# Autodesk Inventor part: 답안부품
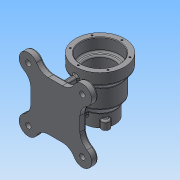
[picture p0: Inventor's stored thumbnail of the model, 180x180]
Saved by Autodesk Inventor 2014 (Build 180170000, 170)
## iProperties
Created: 2017-03
Part Number: 답안부품
Material: 일반
Document SubType Name: Modeling
Designer: NET
Density: 1 g/cm^3
Appearance: 기본값
Author: NET
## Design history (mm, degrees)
sketch "스케치2"
  geometry: L1 (0, 50)-(0, -35); L2 (27.5, -35)-(27.5, -27); L3 (27.5, -27)-(36, -15); L4 (36, -15)-(36, 19); L5 (36, 19)-(45, 30); L6 (45, 30)-(45, 50); L7 (45, 50)-(0, 50); L8 (27.5, -35)-(0, -35); 2 further points
  constraints: 16 end point, 3 parallel, 2 coincident, 2 perpendicular, 1 point on line, 1 vertical
  dimensions: "d6" = 90 diameter of L6.end L1; "d7" = 20 distance of L5.end L6.end; "d8" = 31 vertical distance of L4.end L6.end; "d9" = 65 vertical distance of L6.end L3.end; "d10" = 55 diameter of L2.end L1; "d14" = 72 diameter of L4 L1; "d20" = 85 distance of L1.end L1.start
revolve "회전1" sketch "스케치2" stored, may be unused: angle "d18" = 90 deg
sketch "스케치4"
  geometry: C1 r 27.5 at (0, 0) reference; C2 r 27.5 at (0, 0); C3 r 7 at (0, 27.5); C4 r 7 at (-23.816, -13.75); C5 r 7 at (23.816, -13.75)
  constraints: 4 centre point, 1 coincident, 1 vertical alignment, 7 other
  dimensions: "d21" = 55 diameter of C2; "d22" = 14 diameter of C3; "d23" = 27.5 distance of C1.centre C3.centre; "d26" = 360 deg dimension on C1.centre C3.centre (derived)
extrude "돌출1" join sketch "스케치4" distance "d28" = 15; taper "d29" = 0 deg
fillet "모깎기1" dims "d30" = 3
fillet "모깎기2" dims "d31" = 1
sketch "스케치5"
  geometry: L1 (-45, 50)-(45, 50) reference; L2 (45, 50)-(45, 30) reference; L3 (45, 30)-(36, 19) reference; L4 (36, 19)-(36, -15) reference; L5 (36, -15)-(27.5, -27) reference; L6 (27.5, -27)-(27.5, -34) reference; L7 (28.5, -35)-(31.5, -35) reference; L8 (34.5, -38)-(34.5, -50) reference; L9 (34.5, -50)-(-27.5, -50) reference; L10 (-27.5, -50)-(-27.5, -27) reference; L11 (-27.5, -27)-(-36, -15) reference; L12 (-36, -15)-(-36, 19) reference; L13 (-36, 19)-(-45, 30) reference; L14 (-45, 30)-(-45, 50) reference; L15 (0, 50)-(0, -50); L16 (0, -50)-(17.5, -50); L17 (17.5, -50)-(17.5, -23); L18 (20.5, -20)-(23, -20); L19 (26, -17)-(26, 24); L20 (29, 27)-(32, 27); L21 (35, 30)-(35, 50); L22 (0, 50)-(35, 50); A1 r 1 centre (28.5, -34) between (27.5, -34) and (28.5, -35) reference; A2 r 3 centre (31.5, -38) between (34.5, -38) and (31.5, -35) reference; A3 r 3 centre (32, 30) between (32, 27) and (35, 30); A4 r 3 centre (29, 24) between (29, 27) and (26, 24); A5 r 3 centre (23, -17) between (23, -20) and (26, -17); A6 r 3 centre (20.5, -23) between (20.5, -20) and (17.5, -23); 2 further points
  constraints: 16 end point, 8 point on circle, 8 tangent, 5 point on line, 4 centre point, 4 perpendicular, 2 equal radius, 2 parallel, 1 collinear, 1 midpoint
  dimensions: "d32" = 30 distance of L16.end point (17.5, -20); "d33" = 35 diameter of L17 L15; "d35" = 52 diameter of L19 L15; "d36" = 70 diameter of L21 L15; "d37" = 3 radius of A3; "d38" = 3 radius of A5; "d39" = 47 vertical distance of L20.start L18.end
revolve "회전2" sketch "스케치5" stored, may be unused: angle "d40" = 90 deg
chamfer "모따기1" distance "d41" = 1; stored, may be unused: second distance "d42" = 2, angle "d43" = 45 deg
fillet "모깎기3" dims "d44" = 3
chamfer "모따기2" distance "d45" = 1; stored, may be unused: second distance "d46" = 2, angle "d47" = 45 deg
sketch "스케치6"
  geometry: A1 r 7 centre (0, 27.5) between (6.999, 27.373) and (-6.999, 27.373) reference; 1 further point
  constraints: 1 coincident
hole "구멍1" sketch "스케치6" at (0, 27.5) diameter "d48" = 3.242; stored, may be unused: countersink angle "d52" = 90 deg, drill point angle "d54" = 118 deg; dims "d49" = 9, "d50" = 4, "d51" = 2, "d53" = 11
sketch "스케치11"
  geometry: L1 (-17.5, -49)-(-18.5, -50) reference; L2 (-18.5, -50)-(-27.5, -50) reference; L3 (-27.5, -50)-(-27.5, -27.955) reference; L4 (-28.052, -26.221)-(-35.448, -15.779) reference; L5 (-36, -14.045)-(-36, 17.929) reference; L6 (-36.678, 19.829)-(-44.322, 29.171) reference; L7 (-45, 31.071)-(-45, 50) reference; L8 (-45, 50)-(-36, 50) reference; L9 (-36, 50)-(-35, 49) reference; L10 (-35, 49)-(-35, 30) reference; L11 (-32, 27)-(-29, 27) reference; L12 (-26, 24)-(-26, -17) reference; L13 (-23, -20)-(-20.5, -20) reference; L14 (-17.5, -23)-(-17.5, -49) reference; L15 (34.5, -38)-(34.5, -50) reference; L16 (34.5, -50)-(29.121, -50) reference; L17 (29.121, -50)-(29.121, -39) reference; L18 (29.121, -39)-(27.5, -38.026) reference; L19 (27.5, -38.026)-(25.879, -39) reference; L20 (25.879, -39)-(25.879, -50) reference; L21 (25.879, -50)-(18.5, -50) reference; L22 (18.5, -50)-(17.5, -49) reference; L23 (17.5, -49)-(17.5, -23) reference; L24 (20.5, -20)-(23, -20) reference; L25 (26, -17)-(26, 24) reference; L26 (29, 27)-(32, 27) reference; L27 (35, 30)-(35, 49) reference; L28 (35, 49)-(36, 50) reference; L29 (36, 50)-(45, 50) reference; L30 (45, 50)-(45, 31.071) reference; L31 (44.322, 29.171)-(36.678, 19.829) reference; L32 (36, 17.929)-(36, -14.045) reference; L33 (35.448, -15.779)-(28.052, -26.221) reference; L34 (27.5, -27.955)-(27.5, -34) reference; L35 (28.5, -35)-(31.5, -35) reference; L36 (-36, 1.942)-(-70, 1.942); L37 (-70, 1.942)-(-70, -35.058); L38 (-70, -35.058)-(-27.5, -35.058); A1 r 3 centre (-30.5, -27.955) between (-27.5, -27.955) and (-28.052, -26.221) reference; A2 r 3 centre (-33, -14.045) between (-36, -14.045) and (-35.448, -15.779) reference; A3 r 3 centre (-39, 17.929) between (-36, 17.929) and (-36.678, 19.829) reference; A4 r 3 centre (-42, 31.071) between (-45, 31.071) and (-44.322, 29.171) reference; A5 r 3 centre (-32, 30) between (-35, 30) and (-32, 27) reference; A6 r 3 centre (-29, 24) between (-26, 24) and (-29, 27) reference; A7 r 3 centre (-23, -17) between (-26, -17) and (-23, -20) reference; A8 r 3 centre (-20.5, -23) between (-17.5, -23) and (-20.5, -20) reference; A9 r 3 centre (31.5, -38) between (34.5, -38) and (31.5, -35) reference; A10 r 3 centre (20.5, -23) between (20.5, -20) and (17.5, -23) reference; A11 r 3 centre (23, -17) between (23, -20) and (26, -17) reference; A12 r 3 centre (29, 24) between (29, 27) and (26, 24) reference; A13 r 3 centre (32, 30) between (32, 27) and (35, 30) reference; A14 r 3 centre (42, 31.071) between (44.322, 29.171) and (45, 31.071) reference; A15 r 3 centre (39, 17.929) between (36.678, 19.829) and (36, 17.929) reference; A16 r 3 centre (33, -14.045) between (35.448, -15.779) and (36, -14.045) reference; A17 r 3 centre (30.5, -27.955) between (28.052, -26.221) and (27.5, -27.955) reference; A18 r 1 centre (28.5, -34) between (27.5, -34) and (28.5, -35) reference; 1 further point
  constraints: 6 end point, 2 perpendicular, 1 midpoint, 1 parallel, 1 point on line
  dimensions: "d117" = 37 distance of L36.end L37.end; "d118" = 70 horizontal distance of L36.end point (0, 0)
feature "리브4" sketch "스케치11" dims "d101" = 1, "d102" = 8, "d103" = 0, "d104" = 0, "d105" = 1, "d106" = 1
node "작업 평면3"
sketch "스케치14"
  geometry: L1 (-45, 31.071)-(-45, 50) reference; L2 (-45, 50)-(-36, 50) reference; L3 (-36, 50)-(-35, 49) reference; L4 (-35, 49)-(-35, 30) reference; L5 (-32, 27)-(-29, 27) reference; L6 (-26, 24)-(-26, -17) reference; L7 (-23, -20)-(-20.5, -20) reference; L8 (-17.5, -23)-(-17.5, -49) reference; L9 (-17.5, -49)-(-18.5, -50) reference; L10 (-18.5, -50)-(-27.5, -50) reference; L11 (-27.5, -50)-(-27.5, -35.058) reference; L12 (-27.5, -35.058)-(-70, -35.058) reference; L13 (-70, -35.058)-(-70, 1.942) reference; L14 (-70, 1.942)-(-36, 1.942) reference; L15 (-36, 1.942)-(-36, 17.929) reference; L16 (-36.678, 19.829)-(-44.322, 29.171) reference; L17 (44.322, 29.171)-(36.678, 19.829) reference; L18 (36, 17.929)-(36, -14.045) reference; L19 (35.448, -15.779)-(28.052, -26.221) reference; L20 (27.5, -27.955)-(27.5, -34) reference; L21 (28.5, -35)-(31.5, -35) reference; L22 (34.5, -38)-(34.5, -50) reference; L23 (34.5, -50)-(29.121, -50) reference; L24 (29.121, -50)-(29.121, -39) reference; L25 (29.121, -39)-(27.5, -38.026) reference; L26 (27.5, -38.026)-(25.879, -39) reference; L27 (25.879, -39)-(25.879, -50) reference; L28 (25.879, -50)-(18.5, -50) reference; L29 (18.5, -50)-(17.5, -49) reference; L30 (17.5, -49)-(17.5, -23) reference; L31 (20.5, -20)-(23, -20) reference; L32 (26, -17)-(26, 24) reference; L33 (29, 27)-(32, 27) reference; L34 (35, 30)-(35, 49) reference; L35 (35, 49)-(36, 50) reference; L36 (36, 50)-(45, 50) reference; L37 (45, 50)-(45, 31.071) reference; L38 (-26, 0)-(-70, 0); L39 (-70, 0)-(-70, 37); L40 (-70, 37)-(-45, 37); A1 r 3 centre (-42, 31.071) between (-45, 31.071) and (-44.322, 29.171) reference; A2 r 3 centre (-32, 30) between (-35, 30) and (-32, 27) reference; A3 r 3 centre (-29, 24) between (-26, 24) and (-29, 27) reference; A4 r 3 centre (-23, -17) between (-26, -17) and (-23, -20) reference; A5 r 3 centre (-20.5, -23) between (-17.5, -23) and (-20.5, -20) reference; A6 r 3 centre (-39, 17.929) between (-36, 17.929) and (-36.678, 19.829) reference; A7 r 3 centre (42, 31.071) between (44.322, 29.171) and (45, 31.071) reference; A8 r 3 centre (39, 17.929) between (36.678, 19.829) and (36, 17.929) reference; A9 r 3 centre (33, -14.045) between (35.448, -15.779) and (36, -14.045) reference; A10 r 3 centre (30.5, -27.955) between (28.052, -26.221) and (27.5, -27.955) reference; A11 r 1 centre (28.5, -34) between (27.5, -34) and (28.5, -35) reference; A12 r 3 centre (31.5, -38) between (34.5, -38) and (31.5, -35) reference; A13 r 3 centre (20.5, -23) between (20.5, -20) and (17.5, -23) reference; A14 r 3 centre (23, -17) between (23, -20) and (26, -17) reference; A15 r 3 centre (29, 24) between (29, 27) and (26, 24) reference; A16 r 3 centre (32, 30) between (32, 27) and (35, 30) reference; 1 further point
  constraints: 6 end point, 4 point on line, 1 perpendicular
  dimensions: "d119" = 70 distance of point (0, 0) L38.end; "d120" = 37 distance of L38.end L39.end
feature "리브6" sketch "스케치14" dims "d121" = 1, "d122" = 8, "d123" = 0, "d124" = 0, "d125" = 1, "d126" = 1
node "작업 평면4"
sketch "스케치15"
  geometry: L1 (4, -70)-(-4, -70) reference; L2 (-4, -70)-(-4, -35.777) reference; L3 (4, -35.777)-(4, -70) reference; L4 (0, -70)-(25, -70); L5 (25, -70)-(18.14, -31.096); C1 r 26 at (0, 0) reference; A1 r 36 centre (0, 0) between (4, -35.777) and (-4, -35.777) reference; 1 further point
  constraints: 4 end point, 1 midpoint, 1 perpendicular, 1 point on circle
  dimensions: "d127" = 25 distance of L4.end L4.start; "d129" = 100 deg angle of L5 L4
feature "리브7" sketch "스케치15" dims "d131" = 1, "d132" = 8, "d133" = 0, "d134" = 0, "d135" = 1, "d136" = 1
sketch "스케치16"
  geometry: L1 (18.14, -31.096)-(25, -70) reference; L2 (25, -70)-(-4, -70) reference; L3 (-4, -70)-(-4, -35.777) reference; L4 (0, -70)-(-25, -70); L5 (-25, -70)-(-18.14, -31.096); C1 r 26 at (0, 0) reference; A1 r 36 centre (0, 0) between (18.14, -31.096) and (-4, -35.777) reference; 1 further point
  constraints: 4 end point, 1 point on circle, 1 point on line
  dimensions: "d137" = 25 distance of L4.start L4.end; "d138" = 100 deg angle of L4 L5
feature "리브8" sketch "스케치16" dims "d139" = 1, "d140" = 8, "d141" = 0, "d142" = 0, "d143" = 1, "d144" = 1
sketch "스케치17" dims "d147" = 140
  geometry: L1 (8, 0)-(0, 0) reference; L2 (29, 31.058)-(29, 39.058) reference; L3 (49, 80.058)-(-41, 80.058); L4 (-41, 80.058)-(-41, -9.942); L5 (-41, -9.942)-(49, -9.942); L6 (49, -9.942)-(49, 80.058); L7 (4, 35.058)-(53.497, -14.439); L8 (4, 35.058)-(4, -47.502); C1 r 17 at (53.497, -14.439); C2 r 17 at (53.497, 84.555); C3 r 17 at (-45.497, 84.555); C4 r 17 at (-45.497, -14.439); 5 further points
  constraints: 12 end point, 4 centre point, 4 midpoint, 3 parallel, 2 coincident, 1 horizontal, 1 horizontal alignment, 1 perpendicular, 1 vertical alignment, 12 other
  dimensions: "d145" = 90 distance of L5.end L3.start; "d146" = 90 distance of L4.end L5.end; "d148" = 45 deg angle of L8 L7; "d149" = 34 diameter of C1; "d152" = 360 deg dimension on L7.start C1.centre (derived)
extrude "돌출3" join sketch "스케치17" distance "d154" = 12; taper "d155" = 0 deg
fillet "모깎기10" dims "d156" = 3
fillet "모깎기11" dims "d157" = 3
fillet "모깎기12" dims "d158" = 25
fillet "모깎기13" dims "d159" = 3
sketch "스케치18"
  geometry: C1 r 5 at (-45.497, 14.439); C2 r 5 at (-45.497, -84.555); C3 r 5 at (53.497, -84.555); C4 r 5 at (53.497, 14.439); A1 r 14 centre (-45.497, 14.439) between (-33.279, 21.274) and (-52.332, 2.221) reference; A2 r 14 centre (-45.497, -84.555) between (-52.332, -72.337) and (-33.279, -91.39) reference; A3 r 14 centre (53.497, -84.555) between (41.279, -91.39) and (60.332, -72.337) reference; A4 r 14 centre (53.497, 14.439) between (60.332, 2.221) and (41.279, 21.274) reference; 1 further point
  constraints: 4 centre point, 4 coincident
  dimensions: "d160" = 10 diameter of C1; "d161" = 10 diameter of C2; "d162" = 10 diameter of C3; "d163" = 10 diameter of C4
extrude "돌출4" cut sketch "스케치18" stored distance "d164" = 10 (= d160); taper "d165" = 0 deg
sketch "스케치19" dims "d166" = 80
  geometry: C1 r 45 at (0, 0) reference; 2 further points
  constraints: 2 coincident, 2 vertical alignment, 2 other
hole "구멍2" sketch "스케치19" at (0, 40) diameter "d167" = 3.242; stored, may be unused: countersink angle "d171" = 90 deg, drill point angle "d173" = 118 deg; dims "d168" = 9, "d169" = 4, "d170" = 2, "d172" = 11
node "작업 평면5"
sketch "스케치20"
  geometry: C1 r 5 at (0, 0); 1 further point
  constraints: 1 centre point, 1 coincident
  dimensions: "d178" = 10 diameter of C1
extrude "돌출5" join sketch "스케치20" stored distance "d179" = 10 (= d160); taper "d180" = 0 deg
sketch "스케치21"
  geometry: C1 r 5 at (0, 0) reference; 1 further point
  constraints: 1 coincident
hole "구멍3" sketch "스케치21" at (0, 0) diameter "d181" = 4.134; stored, may be unused: countersink angle "d185" = 90 deg, drill point angle "d187" = 118 deg; dims "d182" = 9, "d183" = 4, "d184" = 2, "d186" = 48.75
fillet "모깎기14" dims "d188" = 3
sketch "스케치22"
  geometry: L1 (3, -75.058)-(5, -75.058) reference; L2 (46, -22.216)-(46, -47.9) reference; L3 (4, -35.058)-(4, -75.058); L4 (16.842, 9.942)-(-8.842, 9.942) reference; 1 further point
  constraints: 2 end point, 1 midpoint, 1 parallel, 1 other
  dimensions: "d190" = 37.94281 horizontal distance of point (41.943, -35.058) L3.end; "d192" = 45 distance from line of L4 point (41.943, -35.058)
feature "엠보싱1" sketch "스케치22" dims "d6" = 90, "d7" = 20, "d8" = 31, "d9" = 65, "d10" = 55, "d14" = 72, "d20" = 85, "d193" = 0.5, "d194" = 0
node "솔리드1"
pattern_circular "원형 패턴1" dims angle "d56" = 360 deg
pattern_circular "원형 패턴2" dims angle "d175" = 360 deg
node "절단 모서리 투영2"
node "절단 모서리 투영7"
node "절단 모서리 투영9"
node "절단 모서리 투영10"
node "절단 모서리 투영11"
